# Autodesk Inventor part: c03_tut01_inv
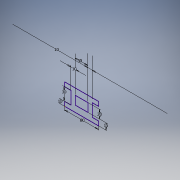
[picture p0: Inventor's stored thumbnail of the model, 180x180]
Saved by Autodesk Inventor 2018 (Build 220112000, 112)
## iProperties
Created: 2017-04
Part Number: c03_tut01_inv
Material: Generic
Document SubType Name: Modeling
Designer: CADCIM 00
Density: 1 g/cm^3
Appearance: Default
Author: CADCIM 00
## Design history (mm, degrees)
sketch "Sketch1"
  geometry: 1 further point
sketch "Sketch2"
  geometry: L1 (0, 0)-(0, 10); L2 (0, 10)-(-15, 10); L3 (-15, 10)-(-15, 40); L4 (-15, 40)-(0, 40); L5 (0, 40)-(0, 50); L6 (0, 50)-(-80, 50); L7 (-80, 50)-(-80, 40); L8 (-80, 40)-(-65, 40); L9 (-65, 40)-(-65, 10); L10 (-65, 10)-(-80, 10); L11 (-80, 0)-(0, 0); L12 (-80, 10)-(-80, 0); L13 (-25, 35)-(-55, 35); L14 (-55, 35)-(-55, 15); L15 (-55, 15)-(-25, 15); L16 (-25, 15)-(-25, 35)
  constraints: 32 end point, 8 perpendicular, 8 point on line, 3 parallel, 2 collinear, 1 horizontal, 1 vertical
  dimensions: "d0" = 80 distance of L11.start L1.start; "d1" = 10 distance of L1.start L1.end; "d2" = 30 distance of L2.end L3.end; "d3" = 10 distance between parallel lines of L16 L3; "d4" = 10 distance between parallel lines of L9 L14; "d5" = 15 distance between parallel lines of L15 L11; "d6" = 20 distance of L13.end L14.end; "d7" = 30 distance of L13.start L13.end
